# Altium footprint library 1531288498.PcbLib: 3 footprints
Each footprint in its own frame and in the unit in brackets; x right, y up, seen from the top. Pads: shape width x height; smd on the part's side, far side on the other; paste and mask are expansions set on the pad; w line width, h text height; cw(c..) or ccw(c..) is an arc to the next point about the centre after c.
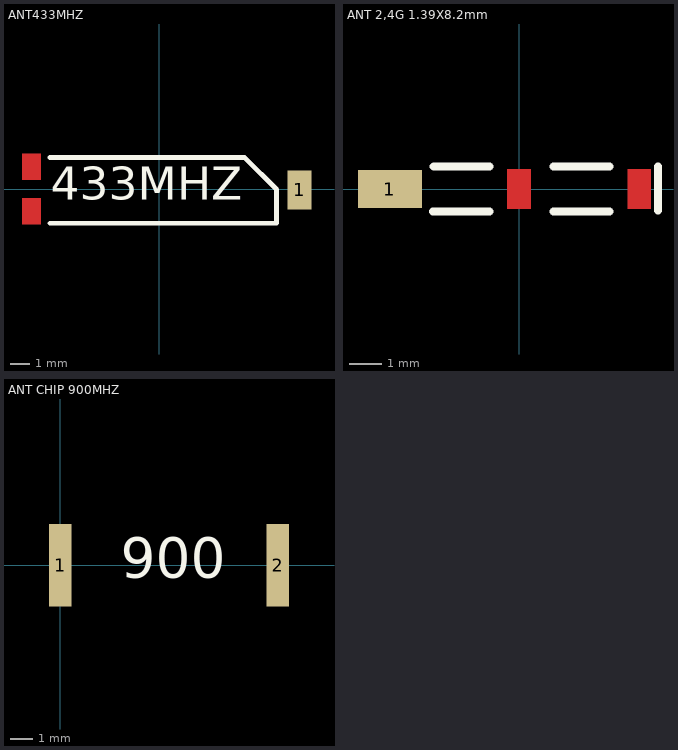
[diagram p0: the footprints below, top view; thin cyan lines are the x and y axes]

## ANT433MHZ [mil]
height 23.62
pads (1):
  rect 50x80 smd: 1(290,-2)
Top Layer:
  region: -244.92,-18.48 -284.29,-18.48 -284.29,-73.6 -244.92,-73.6
  region: -244.92,73.69 -284.29,73.69 -284.29,18.57 -244.92,18.57
Top Overlay:
  lines w10: -226.22,-70.87 242.28,-70.87 242.28,-0.98 176.34,64.96 75.7,64.96 -125.58,64.96 -226.22,64.96
  text "433MHZ" at -225,-45 h118.11
Top Solder:
  region: -240.98,78.61 -290.2,78.61 -290.2,14.64 -240.98,14.64
  region: -240.98,-14.54 -289.21,-14.54 -289.21,-78.52 -240.98,-78.52
Mechanical 1:
  text "IN" at 155,-40 h60
3D body: height 7.87, standoff 0, extent -214.43,-55.68 -138.5,62
3D body: height 7.87, standoff 0, extent -156.43,-58.68 -80.5,59
3D body: height 7.87, standoff 0, extent -97.43,-57.68 -21.5,60
3D body: height 7.87, standoff 0, extent -37.43,-59.68 38.5,58
3D body: height 7.87, standoff 0, extent 7.57,-59.68 83.5,58
3D body: height 7.87, standoff 0, extent 82.57,-61.68 158.5,56
3D body: height 7.87, standoff 0, extent 140.57,-59.68 216.5,58
3D body: height 7.87, standoff 0, extent 196.57,-59.68 272.5,58
3D body: height 51.18, standoff 47.24, extent 167,-60.93 211.22,58
3D body: height 51.18, standoff 47.24, extent -243.22,-59.88 -199,59.06
3D body: height 51.18, standoff 47.24, extent -184.17,-59.88 -139.95,59.06
3D body: height 51.18, standoff 47.24, extent -125.11,-59.88 -80.89,59.06
3D body: height 51.18, standoff 47.24, extent -66.06,-59.88 -21.84,59.06
3D body: height 51.18, standoff 47.24, extent -7,-59.88 37.22,59.06
3D body: height 51.18, standoff 47.24, extent 52.06,-59.88 96.27,59.06
3D body: height 51.18, standoff 47.24, extent 111.11,-59.88 155.33,59.06
3D body: height 51.18, standoff 47.24, extent 167,-60.93 211.22,58
3D body: height 51.18, standoff 0, extent -287,-60 -246,58
3D body: height 51.18, standoff 0, extent 257,-60 298,58
3D body: height 47.24, standoff 0, extent -245,-60.04 256,58.07

## ANT 2,4G 1.39X8.2mm [mm] "1.39X8.2mm"
height 1.08
pads (1):
  rect 2x1.2 smd: 1(-4.05,0)
Top Layer:
  rectangle: 3.4,-0.625 4.125,0.625
  rectangle: -0.375,-0.625 0.375,0.625
Top Overlay:
  lines w0.254: -2.7,-0.7 -0.925,-0.7 ; -2.675,0.7 -0.925,0.7 ; 1.075,-0.7 2.825,-0.7 ; 1.075,0.7 2.825,0.7 ; 4.35,-0.675 4.35,0.7
Top Solder:
  rectangle: 3.375,-0.65 4.15,0.65
  rectangle: -0.4,-0.65 0.4,0.65
Mechanical 13:
  text "2.4G" at 0.508,-0.432 h1.52
3D body: height 1.08, standoff 0, extent -0.575,-0.7 4.1,0.7
3D body: height 1.08, standoff 0, extent -4.075,-0.7 0.6,0.7
3D body: height 1.07, standoff 0, extent -4.087,-0.7 4.088,0.686

## ANT CHIP 900MHZ [mm] "900MHZ"
height 0.6
pads (2):
  rect 1x3.6 smd: 1(0,0) 2(9.5,0)
Top Overlay:
  text "900" at 2.642,-1.118 h3
Top Solder:
  rectangle: 0.914,-1.803 8.661,1.93
3D body: height 1.2, standoff 0, extent 0.864,-1.526 9.779,1.474
3D body: height 1.3, standoff 0, extent -0.203,-1.524 0.838,1.473
3D body: height 1.3, standoff 0, extent 9.004,-1.524 10.046,1.473
3D body: height 1.3, standoff 1.2, extent 2.001,-1.524 3.124,1.497
3D body: height 1.3, standoff 1.2, extent 3.421,-1.551 4.544,1.47
3D body: height 1.3, standoff 1.2, extent 4.921,-1.551 6.044,1.47
3D body: height 1.3, standoff 1.2, extent 6.421,-1.551 7.544,1.47
3D body: height 1.3, standoff 1.2, extent 7.921,-1.551 9.044,1.47
3D body: height 1.3, standoff 1.2, extent 2.001,-1.524 3.124,1.497
3D body: height 0.2, standoff 0, extent 0.445,-1.524 2.373,1.465
3D body: height 0.2, standoff 0, extent 1.867,-1.524 3.796,1.465
3D body: height 0.2, standoff 0, extent 3.34,-1.473 5.269,1.516
3D body: height 0.2, standoff 0, extent 5.245,-1.524 7.174,1.465
3D body: height 0.2, standoff 0, extent 6.388,-1.524 8.317,1.465
3D body: height 0.2, standoff 0, extent 7.912,-1.575 9.841,1.414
